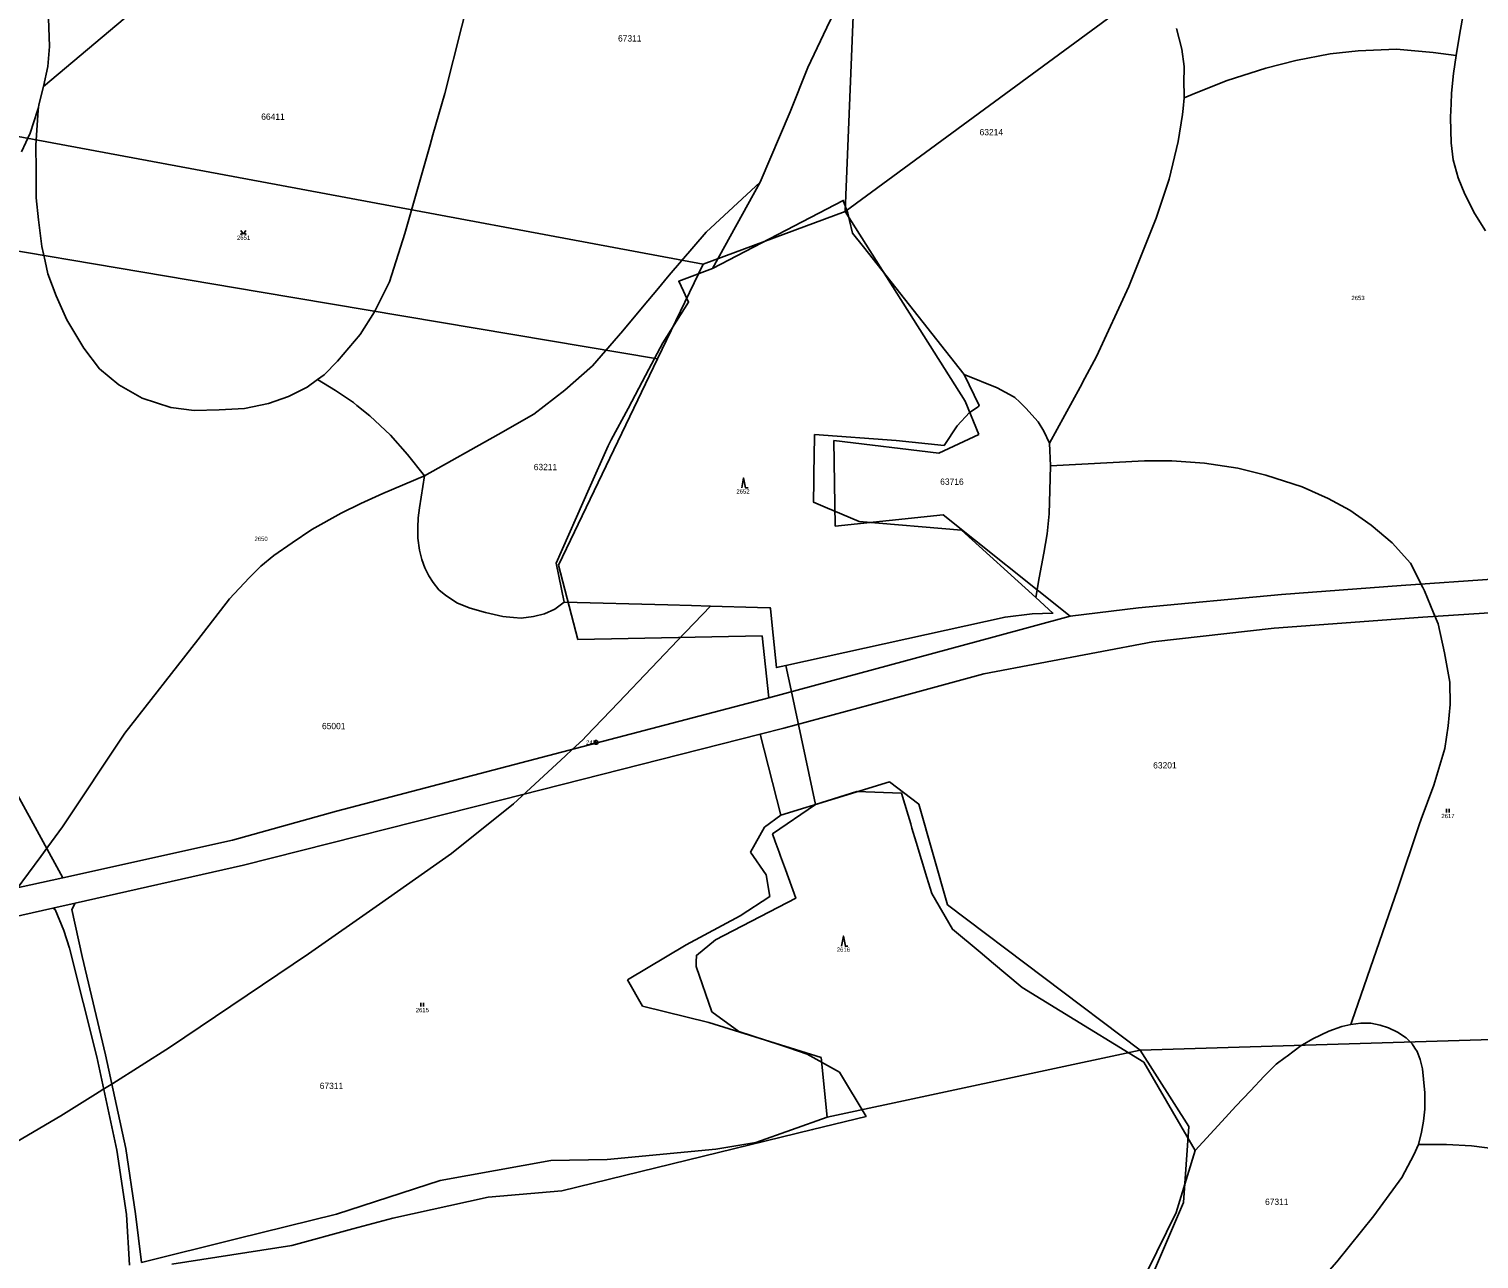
# Model space of a CAD drawing. Extents: x -546762 to -540209, y -1046851 to -1035694.
# Drawn here: x -541746 to -541172, y -1039979 to -1039492 of the extents above; entities that cross this region are included whole.
import ezdxf

# ---------------------------------------------------------------- set-up
doc = ezdxf.new("R2010")
doc.units = 0
for name, color, linetype in [('Vrstva 1', 7, 'Continuous'), ('Vrstva 17', 7, 'Continuous'), ('Vrstva 18', 7, 'Continuous'), ('Vrstva 24', 7, 'Continuous'), ('Vrstva 25', 7, 'Continuous'), ('Vrstva 52', 7, 'Continuous'), ('Vrstva 53', 7, 'Continuous')]:
    doc.layers.add(name, color=color, linetype=linetype)

msp = doc.modelspace()

# ---------------------------------------------------------------- linework, layer by layer
at = {"layer": 'Vrstva 1'}
for points in [[(-541419.43, -1039480.79), (-541422.82, -1039564.73)], [(-541422.82, -1039564.73), (-541316.98, -1039486.91)], [(-541645.88, -1039554.4), (-541812.67, -1039523.33)], [(-541479.08, -1039585.47), (-541645.88, -1039554.4)], [(-541422.82, -1039564.73), (-541479.08, -1039585.47)], [(-541375.37, -1039639.73), (-541422.82, -1039564.73)], [(-541812.43, -1039569.86), (-541654.77, -1039596.43)], [(-541479.08, -1039585.47), (-541497.1, -1039623)], [(-541654.77, -1039596.43), (-541497.1, -1039623)], [(-541497.1, -1039623), (-541536.28, -1039704.61)], [(-541369.92, -1039652.92), (-541375.37, -1039639.73)], [(-541426.76, -1039689.14), (-541427.3, -1039655.35)], [(-541427.3, -1039655.35), (-541385.76, -1039660.28)], [(-541385.76, -1039660.28), (-541369.92, -1039652.92)], [(-541384.02, -1039684.69), (-541426.76, -1039689.14)], [(-541333.83, -1039724.86), (-541384.02, -1039684.69)], [(-541536.28, -1039704.61), (-541528.57, -1039734.01)], [(-541127.1, -1039707.37), (-541202.78, -1039712.68)], [(-541795.79, -1039712.66), (-541732.47, -1039828.3)], [(-541202.78, -1039712.68), (-541250.22, -1039716.28)], [(-541250.22, -1039716.28), (-541306.71, -1039721.57)], [(-541194.29, -1039725.22), (-541066.73, -1039716.93)], [(-541363.84, -1039733), (-541333.83, -1039724.86)], [(-541306.71, -1039721.57), (-541333.83, -1039724.86)], [(-541253.04, -1039729.61), (-541194.29, -1039725.22)], [(-541301.08, -1039734.96), (-541253.04, -1039729.61)], [(-541528.57, -1039734.01), (-541455.74, -1039732.65)], [(-541455.74, -1039732.65), (-541453, -1039757.11)], [(-541453, -1039757.11), (-541363.84, -1039733)], [(-541367.97, -1039747.6), (-541301.08, -1039734.96)], [(-541412.96, -1039759.87), (-541367.97, -1039747.6)], [(-541453, -1039757.11), (-541515.97, -1039773.64)], [(-541447.06, -1039769.16), (-541412.96, -1039759.87)], [(-541456.46, -1039771.54), (-541558.68, -1039797.43)], [(-541456.46, -1039771.54), (-541447.06, -1039769.16)], [(-541448.35, -1039803.55), (-541456.46, -1039771.54)], [(-541515.97, -1039773.64), (-541624.11, -1039802.03)], [(-541405.26, -1039790.42), (-541448.35, -1039803.55)], [(-541393.67, -1039799.16), (-541405.26, -1039790.42)], [(-541558.68, -1039797.43), (-541660.89, -1039823.31)], [(-541382.36, -1039839.09), (-541393.67, -1039799.16)], [(-541624.11, -1039802.03), (-541665.27, -1039813.47)], [(-541448.35, -1039803.55), (-541454.82, -1039808.36)], [(-541454.82, -1039808.36), (-541460.29, -1039818.14)], [(-541665.27, -1039813.47), (-541732.47, -1039828.3)], [(-541460.29, -1039818.14), (-541454.05, -1039827.15)], [(-541660.89, -1039823.31), (-541727.52, -1039838.36)], [(-541732.47, -1039828.3), (-541760.95, -1039834.58)], [(-541454.05, -1039827.15), (-541452.71, -1039835.8)], [(-541868.53, -1039870.22), (-541736.4, -1039840.37)], [(-541736.4, -1039840.37), (-541727.52, -1039838.36)], [(-541736.4, -1039840.37), (-541735.5, -1039840.92)], [(-541735.5, -1039840.92), (-541732.04, -1039849.2)], [(-541727.52, -1039838.36), (-541728.9, -1039840.89)], [(-541728.9, -1039840.89), (-541724.82, -1039859.55)], [(-541452.71, -1039835.8), (-541464.4, -1039843.4)], [(-541306.07, -1039896.52), (-541382.36, -1039839.09)], [(-541464.4, -1039843.4), (-541485.77, -1039854.92)], [(-541732.04, -1039849.2), (-541729.76, -1039856.26)], [(-541729.76, -1039856.26), (-541718.96, -1039899.16)], [(-541485.77, -1039854.92), (-541509.03, -1039868.71)], [(-541724.82, -1039859.55), (-541715.53, -1039898.38)], [(-541509.03, -1039868.71), (-541502.99, -1039879.18)], [(-541502.99, -1039879.18), (-541476.76, -1039885.55)], [(-541476.76, -1039885.55), (-541432.27, -1039899.42)], [(-541166.81, -1039892.34), (-541306.07, -1039896.52)], [(-541715.53, -1039898.38), (-541707.53, -1039935.45)], [(-541429.95, -1039923.14), (-541306.07, -1039896.52)], [(-541306.07, -1039896.52), (-541286.84, -1039926.83)], [(-541718.96, -1039899.16), (-541710.99, -1039936.08)], [(-541432.27, -1039899.42), (-541429.95, -1039923.14)], [(-541429.95, -1039923.14), (-541458.17, -1039933.07)], [(-541286.84, -1039926.83), (-541288.95, -1039956.87)], [(-541710.99, -1039936.08), (-541707.19, -1039961.66)], [(-541707.53, -1039935.45), (-541703.68, -1039961.3)], [(-541474.08, -1039935.72), (-541517, -1039939.79)], [(-541458.17, -1039933.07), (-541474.08, -1039935.72)], [(-541539.34, -1039940.24), (-541583.06, -1039948.12)], [(-541517, -1039939.79), (-541539.34, -1039940.24)], [(-541583.06, -1039948.12), (-541624.06, -1039961.44)], [(-541707.19, -1039961.66), (-541706.05, -1039981.62)], [(-541703.68, -1039961.3), (-541701.35, -1039980.65)], [(-541624.06, -1039961.44), (-541663.7, -1039971.24)], [(-541288.95, -1039956.87), (-541319.8, -1040028.83)], [(-541663.7, -1039971.24), (-541701.35, -1039980.65)]]:
    msp.add_lwpolyline(points, dxfattribs=at)
at = {"layer": 'Vrstva 24'}
for radius in [0.75, 0.1]:
    msp.add_circle((-541521.43, -1039774.77), radius, dxfattribs=at)
at = {"layer": 'Vrstva 25'}
for p, q in [((-541661.94, -1039572.18), (-541660.94, -1039573.68)), ((-541660.94, -1039573.68), (-541659.94, -1039572.18)), ((-541184.83, -1039802.53), (-541184.83, -1039801.03)), ((-541183.83, -1039802.53), (-541183.83, -1039801.03)), ((-541590.69, -1039879.32), (-541590.69, -1039877.82)), ((-541589.69, -1039879.32), (-541589.69, -1039877.82))]:
    msp.add_line(p, q, dxfattribs=at)
for points in [[(-541463.72, -1039674.08), (-541463.02, -1039670.08), (-541462.22, -1039674.08), (-541461.22, -1039674.08)], [(-541424.22, -1039855.42), (-541423.52, -1039851.42), (-541422.72, -1039855.42), (-541421.72, -1039855.42)]]:
    msp.add_lwpolyline(points, dxfattribs=at)
for centre in [(-541661.84, -1039573.63), (-541660.04, -1039573.63)]:
    msp.add_circle(centre, 0.112, dxfattribs=at)
at = {"layer": 'Vrstva 52'}
for points in [[(-541555.58, -1039380.37), (-541595.29, -1039406.4), (-541618.82, -1039420.26), (-541631.69, -1039428.7), (-541648.36, -1039439.62), (-541693.58, -1039475.97), (-541740.02, -1039515.23)], [(-541547.81, -1039384.9), (-541547.96, -1039385.48), (-541567.16, -1039461.82), (-541567.85, -1039464.55), (-541581.29, -1039518.01), (-541585.95, -1039534.35), (-541587.08, -1039538.29), (-541597.09, -1039573.37), (-541603.21, -1039592.5), (-541609.03, -1039604.31), (-541614.71, -1039613.28), (-541623.67, -1039623.89), (-541629.05, -1039629.27), (-541631.58, -1039631.12)], [(-541456.41, -1039553.02), (-541444.64, -1039525.17), (-541437.59, -1039507.65), (-541428.96, -1039489.34), (-541421.38, -1039476.26), (-541413.49, -1039465.64), (-541413.02, -1039465.01)], [(-541181, -1039502.98), (-541179.7, -1039494.87), (-541176.08, -1039474.11)], [(-541738.18, -1039484.43), (-541737.66, -1039499.34), (-541738.38, -1039507.31), (-541740.02, -1039515.23)], [(-541291.73, -1039492.25), (-541289.64, -1039500.47), (-541288.74, -1039507.35), (-541288.82, -1039514), (-541288.72, -1039517.83), (-541288.67, -1039519.68)], [(-541288.67, -1039519.68), (-541283.92, -1039517.76), (-541271.67, -1039512.8), (-541256.43, -1039508.01), (-541244.48, -1039504.88), (-541230.89, -1039502.33), (-541219.84, -1039501.14), (-541204.6, -1039500.39), (-541190.11, -1039501.74), (-541181, -1039502.98)], [(-541169.5, -1039572.33), (-541173.68, -1039565.6), (-541177.57, -1039557.83), (-541180.26, -1039551.4), (-541182.2, -1039544.23), (-541183.09, -1039537.5), (-541183.24, -1039527.66), (-541183.24, -1039527.34), (-541183.08, -1039522.12), (-541182.94, -1039517.78), (-541182.05, -1039510), (-541181, -1039502.98)], [(-541740.02, -1039515.23), (-541741.86, -1039522.46), (-541742.11, -1039523.45)], [(-541288.67, -1039519.68), (-541289.14, -1039523.85), (-541289.41, -1039526.25), (-541291.06, -1039537.01), (-541294.64, -1039551.81)], [(-541742.11, -1039523.45), (-541742.5, -1039524.66), (-541745.4, -1039533.62), (-541748.83, -1039541.09)], [(-541689.7, -1039642.27), (-541701.05, -1039638.53), (-541710.32, -1039633.3), (-541717.93, -1039626.88), (-541724.13, -1039618.77), (-541730.85, -1039607.56), (-541735.04, -1039598), (-541738.32, -1039589.33), (-541739.44, -1039584.28), (-541740.71, -1039578.57), (-541742.06, -1039567.96), (-541742.95, -1039559.29), (-541742.95, -1039548.38), (-541743.1, -1039538.37), (-541742.18, -1039524.57), (-541742.11, -1039523.45)], [(-541589.27, -1039669.22), (-541560.18, -1039652.93), (-541546.07, -1039644.82), (-541533.78, -1039635.41), (-541522.8, -1039625.73), (-541510.78, -1039611.87), (-541502.35, -1039601.75), (-541497.38, -1039595.78), (-541492.48, -1039589.9), (-541477.84, -1039572.9), (-541456.41, -1039553.02)], [(-541456.41, -1039553.02), (-541475.39, -1039587.2)], [(-541294.64, -1039551.81), (-541299.72, -1039567.35), (-541310.56, -1039594.36), (-541323.37, -1039622.09), (-541327.98, -1039630.61), (-541329.9, -1039634.14), (-541341.93, -1039656.35)], [(-541475.39, -1039587.2), (-541423.58, -1039560.29), (-541421.76, -1039565.39), (-541421.09, -1039568.29), (-541419.95, -1039573.19), (-541415.64, -1039578.65), (-541375.79, -1039629.14)], [(-541533.97, -1039719.24), (-541537.25, -1039703.82), (-541524.15, -1039674.31), (-541516.67, -1039657.45), (-541515.41, -1039655.08), (-541508.76, -1039642.58), (-541504.51, -1039634.59), (-541500.5, -1039627.06), (-541494.95, -1039616.64), (-541484.82, -1039600.53), (-541486.85, -1039596.25), (-541488.72, -1039592.29), (-541475.39, -1039587.2)], [(-541631.58, -1039631.12), (-541635.77, -1039634.2), (-541643.09, -1039637.94), (-541651.01, -1039640.63), (-541660.57, -1039642.57), (-541670.57, -1039643.17)], [(-541631.58, -1039631.12), (-541624.46, -1039635.52), (-541619.03, -1039639.23), (-541617.44, -1039640.31), (-541616.06, -1039641.4), (-541610.87, -1039645.54), (-541602.8, -1039653.16), (-541596.08, -1039660.78), (-541589.27, -1039669.22)], [(-541375.79, -1039629.14), (-541369.83, -1039641.42), (-541370.25, -1039642.01), (-541373.6, -1039644.18), (-541378.53, -1039649.49)], [(-541341.93, -1039656.35), (-541344.28, -1039651.64), (-541346.52, -1039647.9), (-541351.3, -1039642.52), (-541353.73, -1039640.18), (-541355.63, -1039638.34), (-541356.35, -1039637.94), (-541362.65, -1039634.45), (-541375.79, -1039629.14)], [(-541670.57, -1039643.17), (-541680.43, -1039643.47), (-541689.7, -1039642.27)], [(-541378.53, -1039649.49), (-541383.7, -1039657.3), (-541402.65, -1039655.27), (-541434.97, -1039652.93), (-541435.02, -1039656.63), (-541435.04, -1039658.31), (-541435.22, -1039671.41), (-541435.33, -1039679.76), (-541429.83, -1039682.08), (-541427.54, -1039683.05), (-541417.36, -1039687.35), (-541376.78, -1039690.76), (-541347.43, -1039717.4)], [(-541341.93, -1039656.35), (-541341.55, -1039665.35)], [(-541341.55, -1039665.35), (-541304.33, -1039663.28), (-541293.54, -1039663.28), (-541280.69, -1039664.32), (-541267.4, -1039666.27), (-541256.35, -1039668.96), (-541242.01, -1039673.59), (-541231.7, -1039678.22), (-541223.19, -1039682.82), (-541214.67, -1039688.8), (-541206.31, -1039695.82), (-541199.14, -1039703.89), (-541194.3, -1039713.43), (-541193.61, -1039714.8), (-541190.02, -1039723.48), (-541188.23, -1039727.8), (-541185.69, -1039739.31), (-541183.6, -1039750.97), (-541183.45, -1039759.75), (-541184.2, -1039768.27), (-541185.54, -1039777.23), (-541189.88, -1039791.73)], [(-541347.43, -1039717.4), (-541346.03, -1039709.59), (-541344.24, -1039699.87), (-541342.9, -1039692.25), (-541342.15, -1039684.33), (-541341.85, -1039675.07), (-541341.55, -1039665.35)], [(-541797.96, -1039896.63), (-541789.75, -1039885.71), (-541784.17, -1039878.2), (-541782.31, -1039875.69), (-541769.44, -1039858.36), (-541760.16, -1039845.73), (-541750.87, -1039833.08), (-541741.18, -1039819.9), (-541738.38, -1039816.09), (-541732.54, -1039808.14), (-541707.95, -1039771.07), (-541678.94, -1039734.2), (-541666.43, -1039717.94), (-541658.62, -1039709.58), (-541654.1, -1039705.05), (-541648.89, -1039700.86), (-541641.72, -1039695.83), (-541633.87, -1039690.45), (-541622.3, -1039683.99), (-541614.45, -1039680.24), (-541605.83, -1039676.31), (-541589.27, -1039669.22)], [(-541554.04, -1039725.3), (-541556.96, -1039725.06), (-541558.28, -1039724.95), (-541565.11, -1039723.41), (-541571.25, -1039721.71), (-541576.2, -1039719.66), (-541580.81, -1039716.67), (-541583.63, -1039714.36), (-541585.85, -1039711.54), (-541587.64, -1039708.9), (-541589.18, -1039705.65), (-541590.37, -1039702.41), (-541591.22, -1039698.73), (-541591.91, -1039693.95), (-541591.99, -1039689.68), (-541591.82, -1039685.84), (-541591.31, -1039682), (-541589.27, -1039669.22)], [(-541533.97, -1039719.24), (-541537.76, -1039722.06), (-541541.86, -1039723.94), (-541546.13, -1039724.96)], [(-541476.08, -1039720.81), (-541483.59, -1039720.61), (-541493.06, -1039720.35), (-541533.97, -1039719.24)], [(-541347.43, -1039717.4), (-541340.6, -1039723.6), (-541348.79, -1039723.89), (-541359.58, -1039725.2), (-541446.3, -1039744.32)], [(-541476.08, -1039720.81), (-541485.85, -1039731.03), (-541486.4, -1039731.6), (-541512.52, -1039758.92), (-541525.31, -1039772.3), (-541526.64, -1039773.69), (-541530.9, -1039777.62), (-541533.63, -1039780.15), (-541554.08, -1039799.06), (-541578.66, -1039818.67), (-541607.15, -1039838.81), (-541635.26, -1039858.48), (-541690.15, -1039895.55), (-541712.7, -1039909.72), (-541716.57, -1039912.15), (-541719.5, -1039913.99), (-541733.15, -1039922.56), (-541745.97, -1039930.1), (-541754.09, -1039934.87), (-541772.75, -1039945.84), (-541777.52, -1039948.65), (-541782.31, -1039951.38), (-541813.66, -1039969.24), (-541838.36, -1039983.43)], [(-541546.13, -1039724.96), (-541551.02, -1039725.55), (-541554.04, -1039725.3)], [(-541451.38, -1039732.27), (-541452.44, -1039721.95), (-541452.49, -1039721.46), (-541457.57, -1039721.32), (-541476.08, -1039720.81)], [(-541446.3, -1039744.32), (-541450.05, -1039745.15), (-541451.38, -1039732.27)], [(-541434.57, -1039799.28), (-541444.21, -1039754.12), (-541446.3, -1039744.32)], [(-541434.57, -1039799.28), (-541418.17, -1039794.21), (-541400.56, -1039794.83), (-541397.94, -1039803.52), (-541396.9, -1039806.98), (-541396.39, -1039808.66), (-541394.7, -1039814.27), (-541390.5, -1039828.17), (-541388.56, -1039834.58), (-541380.35, -1039848.73), (-541369.47, -1039857.82), (-541364.09, -1039862.31), (-541359.25, -1039866.35), (-541352.84, -1039871.7), (-541337.74, -1039881), (-541304.71, -1039901.34), (-541284.31, -1039936.3)], [(-541189.88, -1039791.73), (-541194.96, -1039805.18), (-541195.71, -1039807.42), (-541204.1, -1039832.61), (-541222.4, -1039885.18), (-541222.72, -1039886.36)], [(-541689.27, -1039981.31), (-541641.85, -1039973.8), (-541617.66, -1039967.28), (-541601.81, -1039963), (-541564.09, -1039954.69), (-541534.97, -1039952.23), (-541435.75, -1039927.99), (-541414.55, -1039922.81), (-541425.06, -1039905.32), (-541437.89, -1039898.11), (-541445.53, -1039895.56), (-541448.75, -1039894.49), (-541464.9, -1039889.12), (-541475.56, -1039881.33), (-541481.81, -1039863.42), (-541481.77, -1039861.63), (-541481.71, -1039859.09), (-541474.12, -1039852.96), (-541442.37, -1039836.44), (-541446.5, -1039825.03), (-541448.41, -1039819.75), (-541448.99, -1039818.16), (-541450.5, -1039813.99), (-541451.59, -1039810.97), (-541434.57, -1039799.28)], [(-541222.72, -1039886.36), (-541226.3, -1039887.22), (-541231.42, -1039889.09), (-541237.74, -1039892.08), (-541241.87, -1039894.41), (-541242.44, -1039894.73), (-541247.92, -1039898.92), (-541248.68, -1039899.49), (-541252.27, -1039902.16), (-541257.05, -1039906.86), (-541262.43, -1039912.66), (-541268.23, -1039918.73), (-541273.76, -1039924.77), (-541284.31, -1039936.3)], [(-541195.93, -1039933.84), (-541194.82, -1039928.97), (-541193.97, -1039924.62), (-541193.45, -1039919.92), (-541193.45, -1039913.43), (-541193.97, -1039908.05), (-541194.31, -1039903.95), (-541194.73, -1039902.3), (-541195.25, -1039900.28), (-541196.53, -1039897.12), (-541197.38, -1039895.72), (-541198.4, -1039894.04), (-541200.88, -1039891.65), (-541204.29, -1039889.43), (-541207.79, -1039887.72), (-541211.12, -1039886.7), (-541214.79, -1039885.93), (-541218.72, -1039885.84), (-541222.72, -1039886.36)], [(-541284.31, -1039936.3), (-541290.41, -1039956.05), (-541291.88, -1039960.82), (-541311.16, -1040000), (-541313.2, -1040004.14), (-541315.42, -1040010.54), (-541317.66, -1040016.98), (-541319.39, -1040021.96), (-541320.34, -1040024.31)], [(-541267.48, -1040023.26), (-541252.45, -1040007.83), (-541228.26, -1039980.33), (-541213.62, -1039962.1), (-541202.56, -1039947.01), (-541197.81, -1039937.94), (-541195.93, -1039933.84)], [(-541195.93, -1039933.84), (-541184.84, -1039933.87), (-541174.98, -1039934.47), (-541163.63, -1039935.81), (-541156.91, -1039937.61), (-541150.37, -1039939.26)]]:
    msp.add_lwpolyline(points, dxfattribs=at)

# ---------------------------------------------------------------- texts
at = {"layer": 'Vrstva 17'}
msp.add_text('243', height=1.7, dxfattribs=at).set_placement((-541525.35, -1039775.62))
at = {"layer": 'Vrstva 18'}
for s, p in [('2651', (-541663.51, -1039575.89)), ('2653', (-541222.5, -1039599.74)), ('2652', (-541465.88, -1039676.29)), ('2650', (-541656.58, -1039695.06)), ('2617', (-541186.9, -1039804.74)), ('2616', (-541426.13, -1039857.63)), ('2615', (-541592.77, -1039881.53))]:
    msp.add_text(s, height=1.7, dxfattribs=at).set_placement(p)
at = {"layer": 'Vrstva 53'}
for s, p in [('67311', (-541512.72, -1039497.4)), ('66411', (-541653.91, -1039528.4)), ('63214', (-541369.64, -1039534.5)), ('63211', (-541546.08, -1039667.04)), ('63716', (-541385.23, -1039672.84)), ('65001', (-541629.87, -1039769.54)), ('63201', (-541300.95, -1039785.08)), ('67311', (-541630.76, -1039911.94)), ('67311', (-541256.68, -1039957.8))]:
    msp.add_text(s, height=2.5, dxfattribs=at).set_placement(p)

doc.saveas('drawing.dxf')
